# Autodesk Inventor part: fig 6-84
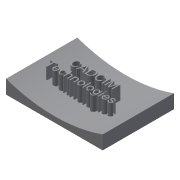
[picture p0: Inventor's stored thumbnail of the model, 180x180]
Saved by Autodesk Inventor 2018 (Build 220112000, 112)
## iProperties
Shininess: 64.0
Length Units: 11269
Angle Units: 11279
Time Units: 11290
Mass Units: 11283
Length Display Precision: 3
Angle Display Precision: 2
Compacted: True
Part Number: fig 6-84
Document SubType Name: Modeling
Created: 2002-12
Designer: deepak
Density: 1 g/cm^3
Material: Generic
Appearance: Default
Density: 0.0
Volumn: 0.0
Area: 0.0
PropertySet Name: Model Information
Control State: 0
Master: False
Checked Out: False
Author: deepak
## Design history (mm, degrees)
sketch "Sketch1"
  geometry: L1 (-39.922, 33.786)-(30.103, 33.786); L2 (30.103, 33.786)-(30.103, -17.894); L3 (30.103, -17.894)-(-39.922, -17.894); L4 (-39.922, -17.894)-(-39.922, 33.786)
  constraints: 8 end point, 2 parallel, 1 horizontal, 1 perpendicular
extrude "Extrusion1" new body sketch "Sketch1" distance "d0" = 10; taper "d1" = 0 deg
workplane "Work Plane1"
sketch "Sketch2"
  geometry: L1 (-37.656, 15.034)-(26.28, 15.034); L2 (26.28, 15.034)-(26.28, 10.168); L3 (26.28, 10.168)-(-37.656, 10.168); L4 (-37.656, 10.168)-(-37.656, 15.034)
  constraints: 2 other
sketch "Sketch3"
  geometry: L1 (70.026, 10)-(0, 10) reference; A1 r 105 centre (35.013, 108.99) between (0, 10) and (70.026, 10)
  constraints: 2 point on circle, 1 centre point
  dimensions: "d5" = 105 radius of A1
extrude "Extrusion2" cut sketch "Sketch3" extent not by distance; stored distance "d3" = 10; taper "d4" = 0 deg
emboss "Emboss4" sketch "Sketch2" dims "d14" = 1, "d15" = 0
body "Solid1"
other parameters: "d2" = 5
